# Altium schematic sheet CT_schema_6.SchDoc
size 368 x 309 mm
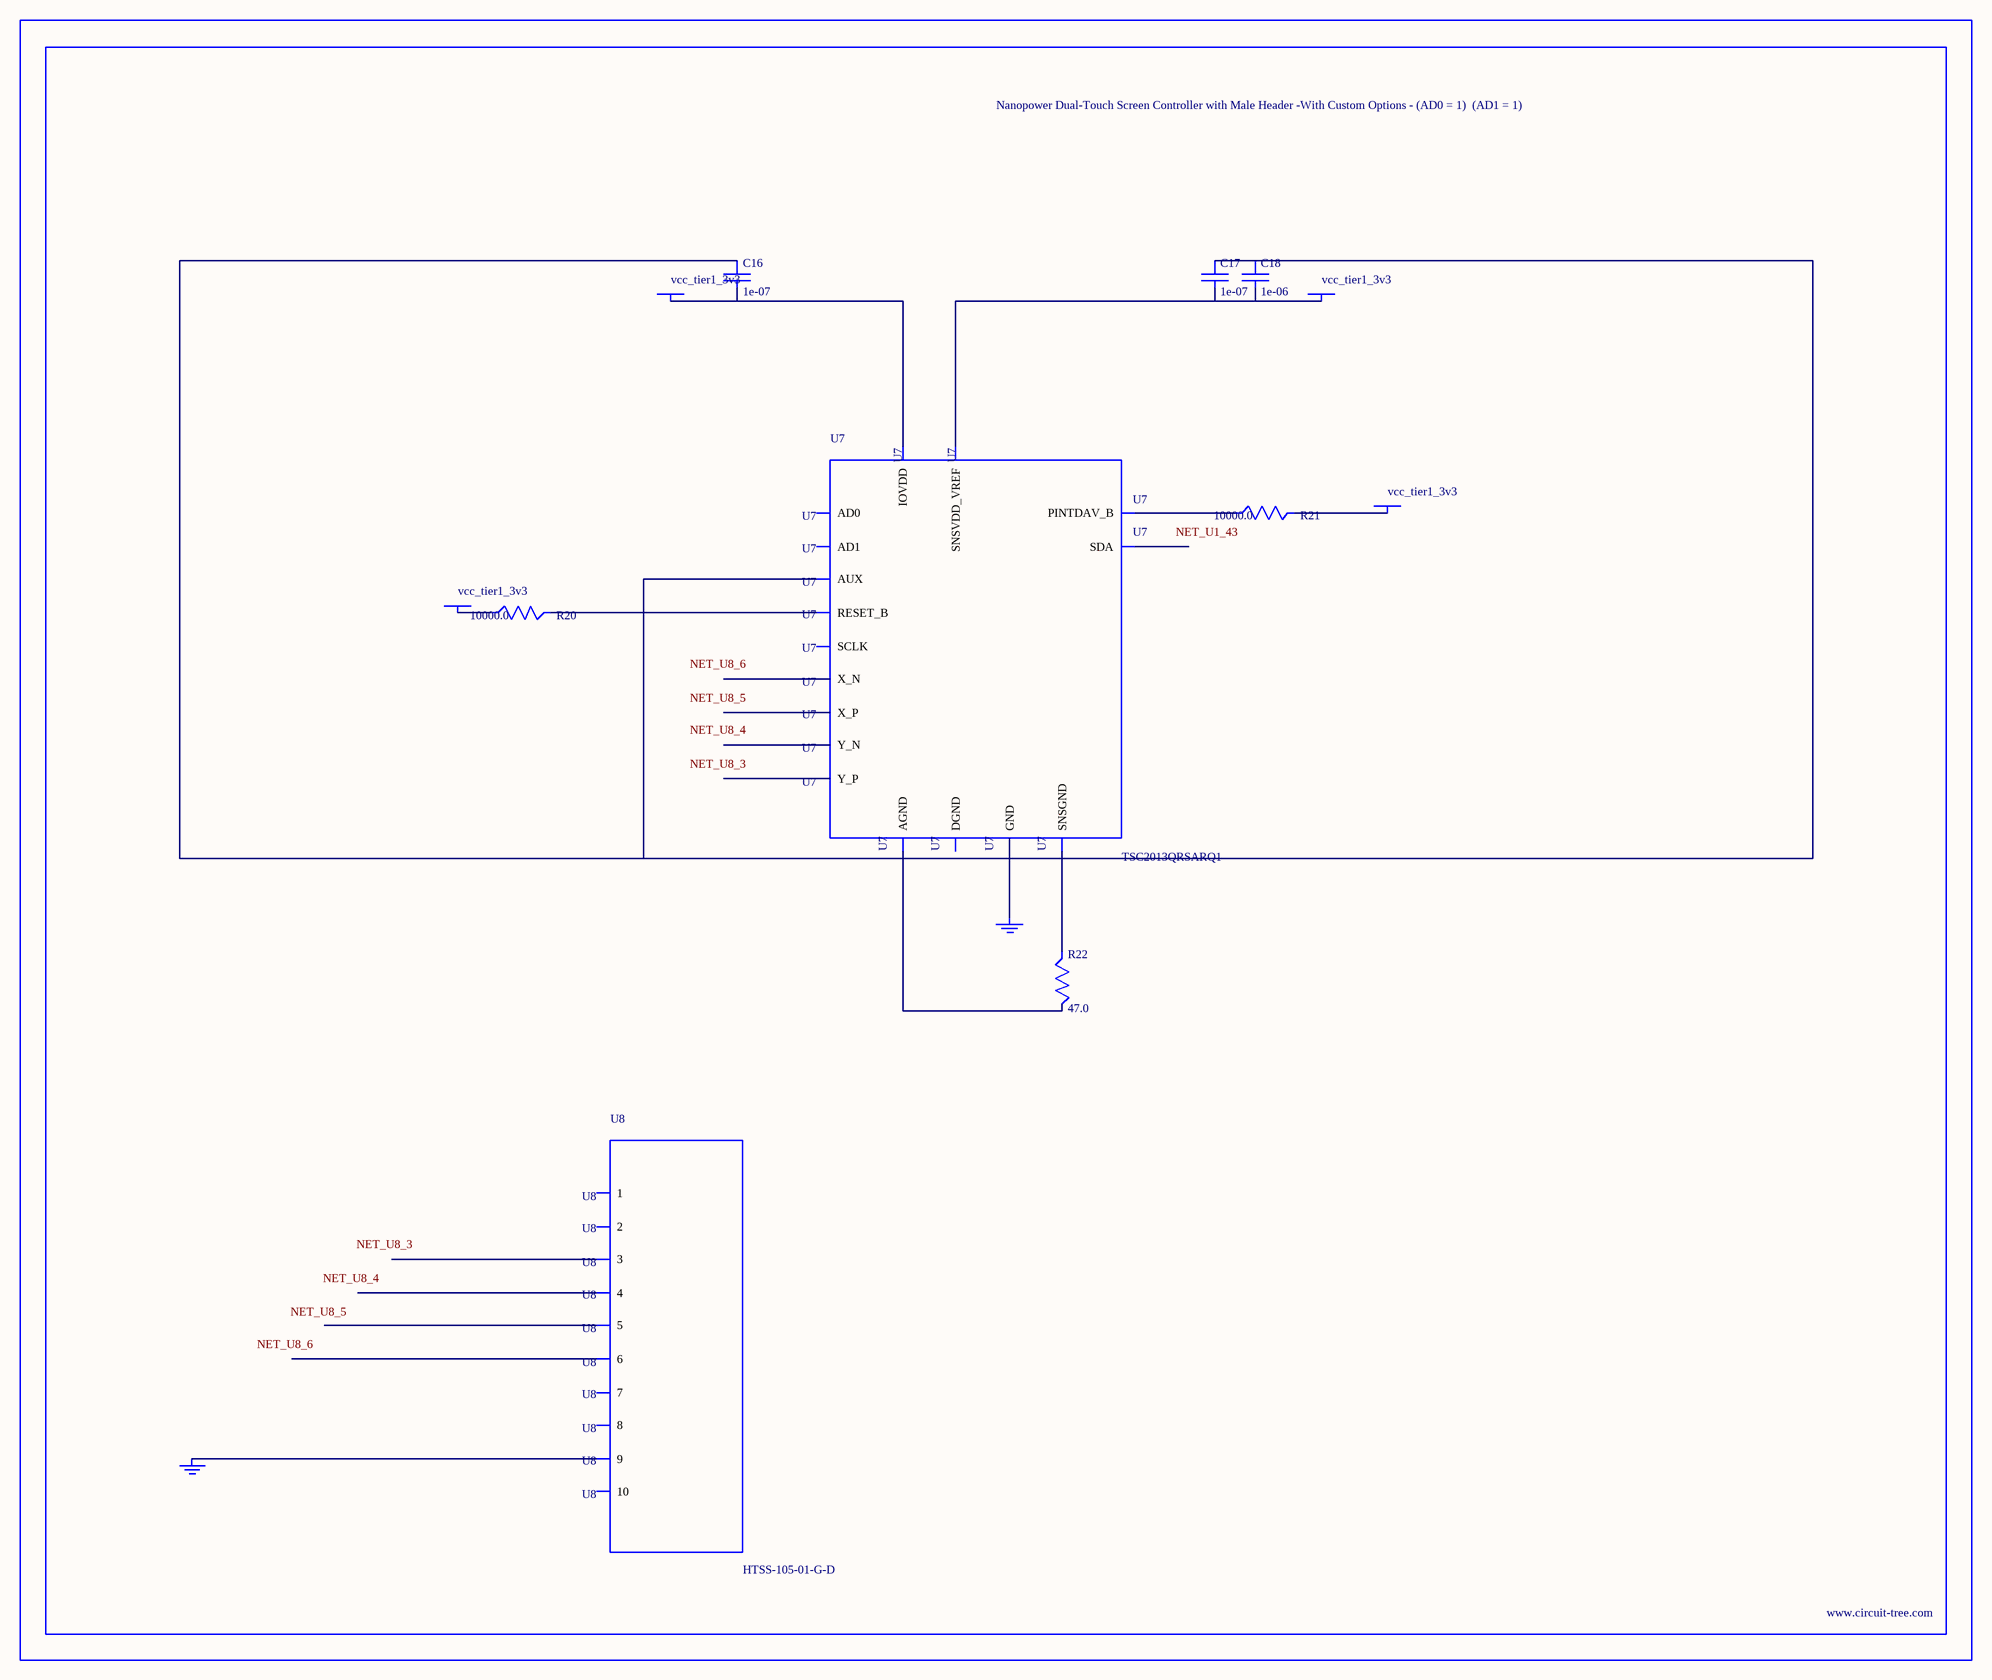
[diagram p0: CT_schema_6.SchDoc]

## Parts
BORDER5  (no value)
C16  1e-07  [C0402]
C17  1e-07  [C0402]
C18  1e-06  [C0603]
GND_INSTANCE_5_0  (no value)
GND_INSTANCE_5_1  (no value)
POWER_INSTANCE_5_0  vcc_tier1_3v3
POWER_INSTANCE_5_1  vcc_tier1_3v3
POWER_INSTANCE_5_2  vcc_tier1_3v3
POWER_INSTANCE_5_3  vcc_tier1_3v3
R20  10000.0  [R0603]
R21  10000.0  [R0603]
R22  47.0  [R0603]
U7  TSC2013QRSARQ1  [QFN65P400X400X100-17N]
U8  HTSS-105-01-G-D  [HTSS-105-01-G-D]

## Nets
NetC16_1: C16.1 C17.1 C18.1 R22.1 R22.2 U7.8(AUX) U7.9(AGND) U7.15(SNSGND)
NetC16_2: C16.2 POWER_INSTANCE_5_2.0(PWR) U7.7(IOVDD)
NetC17_2: C17.2 C18.2 POWER_INSTANCE_5_3.0(PWR) U7.10(SNSVDD_VREF)
NetGND_INSTANCE_5_0_0: GND_INSTANCE_5_0.0(GND) U7.17(GND)
NetGND_INSTANCE_5_1_0: GND_INSTANCE_5_1.0(GND) U8.9
NetPOWER_INSTANCE_5_0_0: POWER_INSTANCE_5_0.0(PWR) R21.2
NetPOWER_INSTANCE_5_1_0: POWER_INSTANCE_5_1.0(PWR) R20.1
NetR20_2: R20.2 U7.5(RESET_B)
NetR21_1: R21.1 U7.4(PINTDAV_B)

Not connected (* = marked no-connect by the designer): U7 1(SDA) 2(SCLK) 3(AD1) 6(DGND) 11(X_P) 12(Y_P) 13(X_N) 14(Y_N) 16(AD0); U8 1 2 3 4 5 6 7 8 10

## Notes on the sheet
- Labels drawn without touching a wire or pin: NET_U1_43, NET_U8_3, NET_U8_4, NET_U8_5, NET_U8_6

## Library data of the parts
BORDER5 = BORDER_PAGE5
C16 C17 = C0402C104K3RACTU
C18 = C0603C105K3RACTU
GND_INSTANCE_5_0 GND_INSTANCE_5_1 = GND
POWER_INSTANCE_5_0-POWER_INSTANCE_5_3 = PWR
R20 R21 = RC0603JR-0710KL
R22 = RC0603JR-0747RL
